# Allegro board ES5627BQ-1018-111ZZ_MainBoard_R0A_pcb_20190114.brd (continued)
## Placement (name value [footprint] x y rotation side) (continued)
C589  22uF/6.3V  [CC0603]  67.46 66.4 90 bottom
C590  22uF/6.3V  [CC0603]  71.78 66.39 90 top
C591  @5pF  [CC0402]  75.47 71.48 180 top
C592  @5pF  [CC0402]  74.44 71.48 180 top
C593  @5pF  [CC0402]  77.44 65.64 180 top
C594  @5pF  [CC0402]  75.41 65.64 180 top
C595  22uF/6.3V  [CC0603]  79.97 66.39 90 bottom
C596  22uF/6.3V  [CC0603]  84.23 66.33 90 top
C597  @5pF  [CC0402]  86.89 71.35 180 top
C598  @5pF  [CC0402]  85.86 71.35 180 top
C599  @5pF  [CC0402]  89.49 65.51 180 top
C600  @5pF  [CC0402]  88.48 65.51 180 top
C601  22uF/6.3V  [CC0603]  110.79 66.39 90 bottom
C602  22uF/6.3V  [CC0603]  115.11 66.39 90 top
C603  @5pF  [CC0402]  118.75 65.05 180 top
C604  @5pF  [CC0402]  117.74 65.05 180 top
C605  @5pF  [CC0402]  120.75 70.57 180 top
C606  @5pF  [CC0402]  119.73 70.57 180 top
C607  22uF/6.3V  [CC0603]  123.36 66.39 90 bottom
C608  22uF/6.3V  [CC0603]  127.68 66.39 90 top
C609  22uF/6.3V  [CC0603]  131.63 66.27 90 bottom
C610  22uF/6.3V  [CC0603]  135.82 66.27 90 top
C611  @5pF  [CC0402]  144.94 65.64 180 top
C612  @5pF  [CC0402]  143.93 65.64 180 top
C613  @5pF  [CC0402]  147.04 71.48 180 top
C614  @5pF  [CC0402]  146.02 71.48 180 top
C615  22uF/6.3V  [CC0603]  149.52 66.4 90 bottom
C616  22uF/6.3V  [CC0603]  153.84 66.39 90 top
C617  @5pF  [CC0402]  157.51 65.64 180 top
C618  @5pF  [CC0402]  156.5 65.64 180 top
C619  @5pF  [CC0402]  159.61 71.48 180 top
C620  @5pF  [CC0402]  158.59 71.48 180 top
C621  22uF/6.3V  [CC0603]  161.91 66.39 90 bottom
C622  22uF/6.3V  [CC0603]  166.35 66.4 90 top
C623  @5pF  [CC0402]  170.09 65.64 180 top
C624  @5pF  [CC0402]  169.07 65.64 180 top
C625  22uF/6.3V  [CC0603]  174.67 66.39 90 bottom
C626  22uF/6.3V  [CC0603]  178.99 66.39 90 top
C627  @5pF  [CC0402]  169.13 71.48 180 top
C628  @5pF  [CC0402]  170.15 71.48 180 top
C629  @5pF  [CC0402]  182.79 71.48 180 top
C630  @5pF  [CC0402]  181.77 71.48 180 top
C631  @5pF  [CC0402]  183.8 71.48 180 top
C632  @5pF  [CC0402]  184.82 71.48 180 top
C633  22uF/6.3V  [CC0603]  187.31 66.39 90 bottom
C634  22uF/6.3V  [CC0603]  191.62 66.39 90 top
C635  @5pF  [CC0402]  193.01 76.46 180 top
C636  @5pF  [CC0402]  195.23 65.49 180 top
C637  2.2uF(25V/10%)  [CC0603]  236.49 64.91 90 bottom
C638  0.1uF/16V  [CC0402]  13.45 71.34 180 top
C639  0.1uF/16V  [CC0402]  14.47 71.34 180 top
C640  0.1uF/16V  [CC0402]  15.48 71.34 180 top
C641  0.1uF/16V  [CC0402]  16.52 71.34 180 top
C642  0.1uF/16V  [CC0402]  17.54 71.34 180 top
C643  0.1uF/16V  [CC0402]  18.56 71.34 180 top
C644  0.1uF/16V  [CC0402]  16.55 65.64 180 top
C645  0.1uF/16V  [CC0402]  17.56 65.64 180 top
C646  0.1uF/16V  [CC0402]  18.56 65.64 180 top
C647  @5pF  [CC0402]  63.03 71.48 180 top
C648  @5pF  [CC0402]  62 71.48 180 top
C649  @5pF  [CC0402]  64.99 65.64 180 top
C650  @5pF  [CC0402]  62.96 65.64 180 top
C651  22uF/6.3V  [CC0603]  29.87 66.39 90 bottom
C652  22uF/6.3V  [CC0603]  34.19 66.39 90 top
C653  22uF/6.3V  [CC0603]  42.32 66.4 90 bottom
C654  22uF/6.3V  [CC0603]  46.7 66.39 270 bottom
C655  22uF/6.3V  [CC0603]  54.95 66.4 90 bottom
C656  22uF/6.3V  [CC0603]  59.27 66.39 270 bottom
C657  @5pF  [CC0402]  142.19 65.56 180 top
C658  @5pF  [CC0402]  141.18 65.56 180 top
C659  @5pF  [CC0402]  142.26 71.4 180 top
C660  @5pF  [CC0402]  141.24 71.4 180 top
C661  @5pF  [CC0402]  27.07 65.62 180 top
C662  @5pF  [CC0402]  25.04 65.62 180 top
C663  @5pF  [CC0402]  36.86 71.48 180 top
C664  @5pF  [CC0402]  38.9 71.48 180 top
C665  @5pF  [CC0402]  39.85 65.64 180 top
C666  @5pF  [CC0402]  38.83 65.64 180 top
C667  @5pF  [CC0402]  50.45 71.48 180 top
C668  @5pF  [CC0402]  49.42 71.48 180 top
C669  @5pF  [CC0402]  52.42 65.64 180 top
C670  @5pF  [CC0402]  51.41 65.64 180 top
C671  0.1uF/16V  [CC0402]  67.08 65.13 90 bottom
C672  0.1uF/16V  [CC0402]  72.29 65.12 90 top
C673  0.1uF/16V  [CC0402]  79.46 65.12 90 bottom
C674  0.1uF/16V  [CC0402]  84.73 65.13 90 top
C675  0.1uF/16V  [CC0402]  110.28 65.12 90 bottom
C676  0.1uF/16V  [CC0402]  115.61 65.12 90 top
C677  0.1uF/16V  [CC0402]  122.85 65.12 90 bottom
C678  0.1uF/16V  [CC0402]  128.19 65.12 90 top
C679  0.1uF/16V  [CC0402]  130.99 65 90 bottom
C680  0.1uF/16V  [CC0402]  136.33 65 90 top
C681  0.1uF/16V  [CC0402]  149.02 65.13 90 bottom
C682  0.1uF/16V  [CC0402]  154.35 65.12 90 top
C683  0.1uF/16V  [CC0402]  161.52 65.12 90 bottom
C684  0.1uF/16V  [CC0402]  166.83 65.12 90 top
C685  0.1uF/16V  [CC0402]  174.16 65.12 90 bottom
C686  0.1uF/16V  [CC0402]  179.5 65.12 90 top
C687  0.1uF/16V  [CC0402]  186.8 65.12 90 bottom
C688  0.1uF/16V  [CC0402]  192.13 65.12 90 top
C689  0.1uF/16V  [CC0402]  29.36 65.12 90 bottom
C690  0.1uF/16V  [CC0402]  34.7 65.12 90 top
C691  0.1uF/16V  [CC0402]  41.93 65.06 90 bottom
C692  0.1uF/16V  [CC0402]  47.2 65.12 270 bottom
C693  0.1uF/16V  [CC0402]  54.51 65.13 90 bottom
C694  0.1uF/16V  [CC0402]  59.78 65.12 270 bottom
C711  @4pF  [CC0402]  248.78 101.67 90 top
C712  @4pF  [CC0402]  250.67 101.67 270 top
C713  @4pF  [CC0402]  246.88 101.67 270 top
C714  @4pF  [CC0402]  244.99 101.67 90 top
C715  @4pF  [CC0402]  258.27 101.67 90 top
C716  @4pF  [CC0402]  256.38 101.67 270 top
C717  @4pF  [CC0402]  252.59 101.67 270 top
C718  @4pF  [CC0402]  254.49 101.67 90 top
C724  0.1uF/16V  [CC0402]  266.35 61.38 180 top
C725  0.1uF/16V  [CC0402]  265.33 61.38 180 top
C735  0.1uF/16V  [CC0402]  264.32 61.38 180 top
C736  0.1uF/16V  [CC0402]  267.36 61.38 180 top
C737  0.1uF/16V  [CC0402]  248.57 67.79 180 bottom
C738  0.1uF/16V  [CC0402]  239.37 76.55 0 top
C739  0.1uF/16V  [CC0402]  240.9 76.55 0 top
C753  0.1UF/50V  [CC0603]  95.82 106.83 270 top
C754  10nF/ 50V  [CC0402]  95.82 105.61 90 top
C771  1uF/16V  [CC0603]  143.41 95.78 270 top
C772  1uF/16V  [CC0603]  143.41 94.32 270 top
C773  10uF/16V  [CC0805]  227.7 134.95 180 top
C774  100pF  [CC0402]  237.13 136.85 0 top
C775  0.1uF/16V  [CC0402]  228.12 137.82 180 top
C776  0.1uF 16V  [CC0402]  224.68 134.67 0 top
C777  0.1uF/16V  [CC0402]  236.12 134.84 0 top
C778  10uF/10V  [CC0402]  235.1 134.83 0 top
C779  10nF  [CC0402]  234.19 113.63 180 bottom
C781  10nF  [CC0402]  232.16 113.63 180 bottom
C783  10nF  [CC0402]  229.17 113.63 180 bottom
C785  10nF  [CC0402]  227.16 113.62 180 bottom
C796  @5pF  [CC0402]  26.05 65.62 180 top
C797  @5pF  [CC0402]  24.02 65.62 180 top
C798  @5pF  [CC0402]  36.8 65.64 180 top
C799  @5pF  [CC0402]  37.82 65.64 180 top
C800  @5pF  [CC0402]  37.88 71.48 180 top
C801  @5pF  [CC0402]  39.91 71.48 180 top
C802  @5pF  [CC0402]  49.36 65.64 180 top
C803  @5pF  [CC0402]  50.39 65.64 180 top
C804  @5pF  [CC0402]  52.49 71.48 180 top
C805  @5pF  [CC0402]  51.47 71.48 180 top
C806  @5pF  [CC0402]  61.93 65.64 180 top
C807  @5pF  [CC0402]  63.98 65.64 180 top
C808  @5pF  [CC0402]  64.04 71.48 180 top
C809  @5pF  [CC0402]  65.06 71.48 180 top
C810  @5pF  [CC0402]  74.38 65.64 180 top
C811  @5pF  [CC0402]  76.42 65.64 180 top
C812  @5pF  [CC0402]  76.49 71.48 180 top
C813  @5pF  [CC0402]  77.5 71.48 180 top
C814  @5pF  [CC0402]  86.43 65.51 180 top
C815  @5pF  [CC0402]  87.46 65.51 180 top
C816  @5pF  [CC0402]  87.9 71.35 180 top
C817  @5pF  [CC0402]  88.92 71.35 180 top
C818  @5pF  [CC0402]  117.7 70.57 180 top
C819  @5pF  [CC0402]  118.72 70.57 180 top
C820  @5pF  [CC0402]  119.77 65.05 180 top
C821  @5pF  [CC0402]  120.79 65.05 180 top
C822  @5pF  [CC0402]  139.21 71.4 180 top
C823  @5pF  [CC0402]  140.22 71.4 180 top
C824  @5pF  [CC0402]  140.16 65.56 180 top
C825  @5pF  [CC0402]  139.15 65.56 180 top
C826  @5pF  [CC0402]  143.99 71.48 180 top
C827  @5pF  [CC0402]  145 71.48 180 top
C828  @5pF  [CC0402]  145.96 65.64 180 top
C829  @5pF  [CC0402]  146.97 65.64 180 top
C830  @5pF  [CC0402]  156.56 71.48 180 top
C831  @5pF  [CC0402]  157.58 71.48 180 top
C832  @5pF  [CC0402]  158.53 65.64 180 top
C833  @5pF  [CC0402]  159.55 65.64 180 top
C834  @5pF  [CC0402]  172.12 65.64 180 top
C835  @5pF  [CC0402]  171.17 71.48 180 top
C836  @5pF  [CC0402]  171.1 65.64 180 top
C837  @5pF  [CC0402]  172.18 71.48 180 top
C838  @5pF  [CC0402]  181.71 65.64 180 top
C839  @5pF  [CC0402]  182.72 65.64 180 top
C840  @5pF  [CC0402]  183.74 65.64 180 top
C841  @5pF  [CC0402]  184.76 65.64 180 top
C842  @5pF  [CC0402]  194.19 65.49 180 top
C843  @5pF  [CC0402]  196.29 65.48 180 top
C844  0.1uF/16V  [CC0402]  182.14 147.67 90 bottom
C845  0.1uF/16V  [CC0402]  182.14 146.65 90 bottom
C846  0.1uF/16V  [CC0402]  182.12 145.65 90 bottom
C847  270uF/16V  [CAPALE_6D3PI_5D6_2SP_6D6WL7D6H]  190.41 131.73 90 top
C848  22uF/16V  [CC1206]  198.24 136.55 90 bottom
C849  0.1uF/16V  [CC0402]  197.96 139.99 270 bottom
C850  0.1uF/16V  [CC0402]  207 148.89 90 top
C851  22uF/16V  [CC1206]  207.19 150.9 90 bottom
C852  270uF/16V  [CAPALE_6D3PI_5D6_2SP_6D6WL7D6H]  208.03 156.01 90 bottom
C853  0.1uF/16V  [CC0402]  132.56 256.77 270 bottom
C854  0.1uF/16V  [CC0402]  132.56 257.79 270 bottom
C855  0.1uF/16V  [CC0402]  124.74 241.59 90 bottom
C856  0.1uF/16V  [CC0402]  124.74 240.57 90 bottom
C857  0.1uF/16V  [CC0402]  132.56 255.76 270 bottom
C858  0.1uF/16V  [CC0402]  124.74 239.56 90 bottom
C859  0.1uF/16V  [CC0402]  124.74 242.61 90 bottom
C860  0.1uF  [CC0402]  263.68 87.54 180 top
C863  1000pF  [CC0402]  250.35 65.19 270 bottom
C864  0.1uF  [CC0402]  234.53 198.45 0 bottom
C865  0.1uF  [CC0402]  236.54 183.72 0 top
C866  0.1uF  [CC0402]  229.45 189.01 270 bottom
C867  0.1uF  [CC0402]  235.87 190.79 90 bottom
C868  0.1uF  [CC0402]  235.93 196 90 bottom
C869  0.1uF  [CC0402]  187.6 177.39 90 top
C870  0.1uF  [CC0402]  231.99 198.45 180 bottom
C871  4.7uF  [CC0402]  234.5 183.72 0 top
C872  4.7uF  [CC0402]  231.51 183.73 0 top
C873  0.1uF  [CC0402]  232.5 183.72 0 top
C874  0.1uF  [CC0402]  235.52 183.72 0 top
C875  4.7uF  [CC0402]  227.45 197.49 90 bottom
C876  0.1uF/16V  [CC0402]  229.52 193.01 270 bottom
C877  0.1uF/16V  [CC0402]  227.45 196.5 90 bottom
C878  10uF  [CC0402]  228.59 169.62 0 bottom
C879  0.1uF  [CC0402]  227.57 169.62 0 bottom
C880  18pF  [CC0402]  226.96 184.22 270 top
C881  0.1uF  [CC0402]  223.83 163.9 0 bottom
C882  0.1uF  [CC0402]  223.47 167.03 180 bottom
C883  0.1uF  [CC0402]  227.08 163.85 0 bottom
C884  18pF  [CC0402]  230.03 184.22 270 top
C885  @4pF  [CC0402]  234.87 110.63 270 top
C886  @4pF  [CC0402]  236.77 110.63 90 top
C887  @4pF  [CC0402]  231.06 110.63 270 top
C888  @4pF  [CC0402]  232.96 110.63 90 top
C889  0.1uF/16V  [CC0402]  237.33 75.41 90 bottom
C890  @4pF  [CC0402]  229.15 110.63 270 top
C891  @4pF  [CC0402]  227.18 110.63 90 top
C892  @4pF  [CC0402]  225.28 110.63 270 top
C893  @4pF  [CC0402]  223.37 110.63 90 top
C894  0.1uF  [CC0402]  226.79 94.14 90 bottom
C895  10nF  [CC0402]  230.6 94.14 270 bottom
C896  1000pF  [CC0402]  222.98 94.14 270 bottom
C897  1000pF  [CC0402]  235.42 74.39 90 bottom
C898  0.1uF  [CC0402]  259.93 87.54 180 top
C899  0.1uF  [CC0402]  256.64 84.81 90 bottom
C900  0.1uF  [CC0402]  252.89 84.81 90 bottom
C901  10uF  [CC0402]  103.34 228.62 0 bottom
C904  0.1uF/16V  [CC0402]  119.48 204.33 0 top
C905  0.1uF/16V  [CC0402]  118.47 204.35 0 top
C908  0.1uF/16V  [CC0402]  138.23 181.97 270 top
C909  0.1uF/16V  [CC0402]  138.23 183.17 270 top
C914  0.1uF/16V  [CC0402]  157.1 170.19 90 bottom
C915  1uF  [CC0402]  156.07 186.18 180 top
C916  1uF  [CC0402]  161.13 178.92 90 top
C917  0.1uF/16V  [CC0402]  146.26 189.3 180 top
C918  0.1uF/16V  [CC0402]  145.25 189.31 180 top
C919  10nF  [CC0402]  43.89 207.66 90 top
C922  10nF  [CC0402]  108.04 178.72 270 top
C923  1uF  [CC0402]  108.04 177.71 270 top
C924  10nF  [CC0402]  142.71 165.39 0 top
C925  0.1uF/16V  [CC0402]  108.04 179.74 90 top
C926  0.1uF/16V  [CC0402]  43.89 208.67 270 top
C927  0.1uF/16V  [CC0402]  143.73 165.39 180 top
C928  0.1uF/16V  [CC0402]  161.13 179.93 90 top
C929  0.1uF/16V  [CC0402]  146.66 179.9 270 bottom
C930  0.1uF/16V  [CC0402]  147.41 175.61 270 bottom
C931  0.1uF/16V  [CC0402]  145.07 184.34 90 bottom
C932  0.1uF/16V  [CC0402]  144.24 175.36 90 bottom
C933  0.1uF/16V  [CC0402]  146.71 177.13 270 bottom
C934  0.1uF/16V  [CC0402]  147.79 186.27 180 top
C935  0.1uF/16V  [CC0402]  147.68 172.97 0 bottom
C936  0.1uF/16V  [CC0402]  152.36 172.97 0 bottom
C937  0.1uF/16V  [CC0402]  150.1 172.96 0 bottom
C938  0.1uF/16V  [CC0402]  156.05 183.36 180 bottom
C939  0.1uF/16V  [CC0402]  158.02 180.69 90 bottom
C940  0.1uF/16V  [CC0402]  158.09 171.65 180 bottom
C941  0.1uF/16V  [CC0402]  146.74 170.5 180 bottom
C942  0.1uF/16V  [CC0402]  151.36 172.97 0 bottom
C943  0.1uF/16V  [CC0402]  146.53 185.82 0 bottom
C944  0.1uF/16V  [CC0402]  148.36 183.3 180 bottom
C945  0.1uF/16V  [CC0402]  153.8 172.69 270 bottom
C946  0.1uF/16V  [CC0402]  144.24 181.39 90 bottom
C947  0.1uF/16V  [CC0402]  144.24 174.34 90 bottom
C948  0.1uF/16V  [CC0402]  149.08 172.96 0 bottom
C949  0.1uF/16V  [CC0402]  146.7 178.24 270 bottom
C952  0.1uF/16V  [CC0402]  255.04 48.49 0 top
C953  0.1uF/16V  [CC0402]  255.04 48.49 180 bottom
C954  0.1uF/16V  [CC0402]  213.13 26.16 180 bottom
C955  0.1uF/16V  [CC0402]  213.6 9.81 90 bottom
C956  0.1uF/16V  [CC0402]  256.06 48.49 180 bottom
C957  0.1uF/16V  [CC0402]  223.55 33.32 270 bottom
C958  0.1uF/16V  [CC0402]  228.61 33.4 180 top
C959  0.1uF/16V  [CC0402]  223.57 33.31 90 top
C960  0.1uF/16V  [CC0402]  137.04 92.89 180 top
C961  0.1uF/16V  [CC0402]  138.03 92.88 180 top
C962  0.1uF/16V  [CC0402]  139.03 92.87 180 top
C963  0.1uF/16V  [CC0402]  140.03 92.87 180 top
C964  0.1uF/16V  [CC0402]  198.75 92.97 180 top
C965  0.1uF/16V  [CC0402]  199.74 92.97 180 top
C966  0.1uF/16V  [CC0402]  201.74 92.98 180 top
C967  0.1uF/16V  [CC0402]  200.74 92.98 180 top
C968  0.1uF/16V  [CC0402]  265.27 189.67 180 top
C969  0.1uF/16V  [CC0402]  266.26 189.67 180 top
C970  0.1uF/16V  [CC0402]  264.26 189.66 180 top
C971  0.1uF/16V  [CC0402]  263.27 189.66 180 top
C972  0.1uF/16V  [CC0402]  206.98 112.37 90 top
C973  0.1uF/16V  [CC0402]  206.98 113.38 90 top
C974  0.1uF/16V  [CC0402]  206.98 111.29 90 top
C975  0.1uF/16V  [CC0402]  206.98 114.4 90 top
C976  0.1uF/16V  [CC0402]  131.26 116.42 180 top
C977  0.1uF/16V  [CC0402]  132.28 116.42 180 top
C978  0.1uF/16V  [CC0402]  133.27 116.41 180 top
C979  0.1uF/16V  [CC0402]  134.28 116.41 180 top
C980  0.1uF/16V  [CC0402]  129.15 234.71 180 top
C981  0.1uF/16V  [CC0402]  130.16 234.71 180 top
C982  0.1uF/16V  [CC0402]  131.16 234.71 180 top
C983  0.1uF/16V  [CC0402]  132.16 234.7 180 top
C984  0.1uF/16V  [CC0402]  63.59 215.49 90 top
C985  0.1uF/16V  [CC0402]  63.59 217.52 270 top
C986  0.1uF/16V  [CC0402]  103.53 251.11 270 bottom
C987  0.1uF/16V  [CC0402]  138.22 175.3 270 top
C988  0.1uF/16V  [CC0402]  138.23 176.5 270 top
C989  0.1uF/16V  [CC0402]  207.82 10.14 270 bottom
C990  0.1uF/16V  [CC0402]  222.22 42.95 180 bottom
C991  0.1uF/16V  [CC0402]  222.23 40.17 0 top
C992  0.1uF/16V  [CC0402]  211.09 18.23 0 bottom
C993  0.1uF/16V  [CC0402]  246.47 147.39 180 top
C994  0.1uF/16V  [CC0402]  247.46 147.39 180 top
C995  0.1uF/16V  [CC0402]  245.46 147.39 180 top
C996  0.1uF/16V  [CC0402]  248.45 147.39 180 top
C997  0.1uF/16V  [CC0402]  207.46 147.24 180 top
C998  0.1uF/16V  [CC0402]  212.64 139.42 90 top
C999  0.1uF/16V  [CC0402]  212.64 140.46 90 top
C1000  0.1uF/16V  [CC0402]  208.5 147.24 180 top
C1001  0.1uF/16V  [CC0402]  123.13 136.12 270 top
C1002  0.1uF/16V  [CC0402]  123.13 135.07 270 top
C1003  0.1uF/16V  [CC0402]  126.66 133.45 0 top
C1004  0.1uF/16V  [CC0402]  127.7 133.45 0 top
CB2  0.1uF/16V  [CC0402]  90.29 182.51 270 bottom
CB3  10uF/6.3V  [CC0603]  90.61 182.45 90 top
CB4  0.1uF/16V  [CC0402]  61.69 223.24 0 top
CB5  0.1uF/16V  [CC0402]  86.92 183.59 180 bottom
CB6  10uF/6.3V  [CC0603]  92.96 183.57 0 top
CB7  9pF/50V  [CC0402]  82.42 183.83 180 top
CB8  9pF/50V  [CC0402]  84.45 183.83 0 top
CB9  22uF  [CC0603]  86.88 183.27 0 top
CB10  10pF  [CC0402]  91.56 184.08 180 top
CB12  0.1uF/16V  [CC0402]  37.43 238.92 0 bottom
CB13  0.1uF/16V  [CC0402]  33.05 238.92 0 bottom
CB21  0.1UF 50V  [CC0603]  140.43 232.26 0 top
CB24  0.1uF/16V  [CC0402]  57.81 223.24 180 top
CB25  10uF/6.3V  [CC0603]  89.78 186.62 0 top
CB26  22uF  [CC0603]  91.43 186.62 0 top
CB27  0.1uF/16V  [CC0402]  167.55 173.03 180 top
CB28  22uF/6.3V  [CC0805]  209.8 207.02 0 bottom
CB29  10uF/6.3V  [CC0603]  168.73 173.29 0 top
CB30  0.1uF/16V  [CC0402]  33.18 223.11 180 top
CB31  0.1uF/16V  [CC0402]  58.83 223.24 0 top
CB32  0.1uF/16V  [CC0402]  90.04 188.65 90 top
CB33  0.1uF 16V  [CC0402]  231.06 224.09 270 bottom
CB34  0.1uF/16V  [CC0402]  80.67 189.58 0 bottom
CB35  0.1uF/16V  [CC0402]  49.94 238.92 0 bottom
CB36  0.1uF/16V  [CC0402]  37.37 223.11 180 top
CB38  0.1uF/16V  [CC0402]  70.96 238.92 0 bottom
CB39  0.1uF/16V  [CC0402]  45.81 238.92 0 bottom
CB42  0.1uF/16V  [CC0402]  83.18 193.99 180 top
CB43  0.1uF/16V  [CC0402]  85.72 193.99 180 top
CB44  0.1uF/16V  [CC0402_22X22_8OCT]  191.06 199.6 180 bottom
CB45  0.1uF/16V  [CC0402_22X22_8OCT]  206.04 199.6 180 bottom
CB46  10uF/6.3V  [CC0603]  84.45 194.49 180 top
CB47  10uF/6.3V  [CC0603]  86.99 194.49 180 top
CB48  22uF  [CC0603]  88.51 194.49 180 top
CB49  10uF/6.3V  [CC0603]  91.56 194.49 0 top
CB50  10pF  [CC0402]  92.93 194.66 180 top
CB51  0.1uF/16V  [CC0402_22X22_8OCT]  190.04 198.58 0 bottom
CB52  10uF/10V  [CC0402]  19.02 178.03 0 bottom
CB53  0.1uF/16V  [CC0402]  20.03 178.03 0 bottom
CB54  0.1uF/16V  [CC0402]  21.05 178.03 0 bottom
CB55  1uF/25V  [CC0402]  22.06 178.03 0 bottom
CB56  0.1uF/16V  [CC0402]  22.95 178.03 0 bottom
CB57  0.1uF/16V  [CC0402]  24.1 178.03 0 bottom
CB58  22nF/16V  [CC0402]  24.98 178.03 180 bottom
CB59  1uF/25V  [CC0402]  26 178.03 0 bottom
CB60  0.01uF/25V  [CC0402]  27.02 178.03 180 bottom
CB61  10uF/10V  [CC0402]  28.03 178.03 0 bottom
CB62  1uF/25V  [CC0402]  30.06 178.03 0 bottom
CB63  10uF/10V  [CC0402]  31.08 178.03 0 bottom
CB64  22nF/16V  [CC0402]  32.12 178.03 180 bottom
CB65  0.1uF/16V  [CC0402]  83.4 177.9 0 bottom
CB66  0.1uF/16V  [CC0402]  84.42 177.9 0 bottom
CB67  0.01uF/25V  [CC0402]  85.44 177.9 180 bottom
CB68  0.01uF/25V  [CC0402]  86.45 177.9 180 bottom
CB69  0.1uF/16V  [CC0402]  87.47 177.9 0 bottom
CB70  0.1uF/16V  [CC0402]  88.48 177.9 0 bottom
CB71  22nF/16V  [CC0402]  92.68 177.9 180 bottom
CB72  0.1uF/16V  [CC0402_22X22_8OCT]  207.57 197.06 270 bottom
CB73  1uF/25V  [CC0402]  81.32 177.87 0 bottom
CB74  22nF/16V  [CC0402]  82.34 177.87 180 bottom
CB75  10uF/10V  [CC0402]  90.52 177.87 0 bottom
CB76  0.1uF/16V  [CC0402]  91.66 177.87 0 bottom
CB77  0.1uF/16V  [CC0402]  69.59 177.8 0 bottom
CB78  22nF/16V  [CC0402]  70.58 177.8 180 bottom
CB79  0.1uF/16V  [CC0402]  60.42 177.77 0 bottom
CB80  22nF/16V  [CC0402]  61.43 177.77 180 bottom
CB81  10uF/10V  [CC0402]  62.45 177.77 0 bottom
CB82  0.1uF/16V  [CC0402]  63.47 177.77 0 bottom
CB83  0.1uF/16V  [CC0402]  64.48 177.77 0 bottom
CB84  1uF/25V  [CC0402]  65.5 177.77 0 bottom
CB85  0.01uF/25V  [CC0402]  66.51 177.77 180 bottom
CB86  22nF/16V  [CC0402]  67.53 177.77 180 bottom
CB87  10uF/10V  [CC0402]  68.55 177.77 0 bottom
CB90  0.01uF/25V  [CC0402]  96.74 174.85 270 bottom
CB92  0.1uF/16V  [CC0402_22X22_8OCT]  197.03 193.63 180 bottom
CB101  0.1uF/16V  [CC0402_22X22_8OCT]  200.58 193.12 270 bottom
CB104  0.1uF/16V  [CC0402_22X22_8OCT]  199.06 192.61 180 bottom
CB108  0.1uF/16V  [CC0402_22X22_8OCT]  195.5 192.1 270 bottom
CB109  0.1uF/16V  [CC0402_22X22_8OCT]  201.5 192.08 90 bottom
CB110  1uF/25V  [CC0402]  85.18 172.69 270 bottom
CB113  0.1uF/16V  [CC0402_22X22_8OCT]  197.03 191.59 0 bottom
CB114  0.1uF/16V  [CC0402_22X22_8OCT]  200.08 191.59 180 bottom
CB118  22nF/16V  [CC0402]  40.86 172.06 0 bottom
CB119  1uF/25V  [CC0402]  41.88 172.06 0 bottom
CB120  0.01uF/25V  [CC0402]  101.44 172.69 90 bottom
CB121  0.1uF/16V  [CC0402_22X22_8OCT]  201.47 191.06 270 bottom
CB122  0.1uF/16V  [CC0402]  81.37 171.88 0 bottom
CB124  1uF/25V  [CC0402]  92.19 171.5 0 bottom
CB125  0.1uF/16V  [CC0402]  75.66 171.42 90 bottom
CB128  0.1uF/16V  [CC0402_22X22_8OCT]  196.52 190.2 90 bottom
CB129  0.1uF/16V  [CC0402_22X22_8OCT]  200.58 190.2 270 bottom
CB130  22nF/16V  [CC0402]  41.24 170.66 270 bottom
CB131  1uF/25V  [CC0402]  49.75 170.66 90 bottom
CB134  0.1uF/16V  [CC0402]  90.41 170.53 0 bottom
CB135  22nF/16V  [CC0402]  75.66 170.41 270 bottom
CB136  22nF/16V  [CC0402]  80.99 170.41 90 bottom
CB138  0.1uF/16V  [CC0402_22X22_8OCT]  195.1 189.56 0 bottom
CB139  0.01uF/25V  [CC0402]  14.95 170.28 90 bottom
CB140  22uF/6.3V  [CC0805]  198.55 189.44 180 bottom
CB141  1uF/25V  [CC0402]  60.04 171.52 90 bottom
CB152  1uF/25V  [CC0402]  92.19 169.62 180 bottom
CB153  0.1uF/16V  [CC0402_22X22_8OCT]  196.09 188.57 180 bottom
CB154  22uF/6.3V  [CC0603]  41.75 169.39 270 bottom
CB155  0.1uF/16V  [CC0402_22X22_8OCT]  201.09 188.55 180 bottom
CB156  0.01uF/25V  [CC0402]  12.41 169.26 270 bottom
CB157  0.01uF/25V  [CC0402]  60.04 170.51 90 bottom
CB159  0.1uF/16V  [CC0402]  101.03 168.78 0 bottom
CB160  0.1uF/16V  [CC0402]  90.49 168.42 0 bottom
CB161  0.1uF/16V  [CC0402_22X22_8OCT]  197.03 187.53 0 bottom
CB162  0.1uF/16V  [CC0402_22X22_8OCT]  200.08 187.53 0 bottom
CB166  0.01uF/25V  [CC0402]  12.41 168.12 270 bottom
CB167  0.01uF/25V  [CC0402]  60.04 169.52 90 bottom
CB170  0.1uF/16V  [CC0402_22X22_8OCT]  198.55 187.05 270 bottom
CB172  0.01uF/25V  [CC0402]  91.79 167.74 0 bottom
CB173  0.01uF/25V  [CC0402]  49.09 167.51 180 bottom
CB175  22nF/16V  [CC0402]  50.08 167.49 180 bottom
CB176  1uF/25V  [CC0402]  75.66 167.36 90 bottom
CB177  0.01uF/25V  [CC0402]  60.16 167.23 270 bottom
CB181  1uF/25V  [CC0402]  101.06 166.93 180 bottom
CB182  1uF/25V  [CC0402]  69.89 166.85 180 bottom
CB183  0.01uF/25V  [CC0402]  71.34 166.82 270 bottom
CB185  1uF/25V  [CC0402]  90.39 166.55 180 bottom
CB186  0.01uF/25V  [CC0402]  12.67 166.34 90 bottom
CB193  22nF/16V  [CC0402]  91.79 165.83 0 bottom
CB195  0.1uF/16V  [CC0402]  71.34 165.81 270 bottom
CB196  0.01uF/25V  [CC0402]  41.24 165.71 270 bottom
CB197  0.01uF/25V  [CC0402]  81.37 165.71 0 bottom
CB198  0.1uF/16V  [CC0402]  49.06 165.61 180 bottom
CB199  1uF/25V  [CC0402]  50.08 165.61 180 bottom
CB201  0.1uF/16V  [CC0402]  12.67 165.33 90 bottom
CB202  0.1uF/16V  [CC0402]  14.95 165.33 270 bottom
CB203  0.1uF/16V  [CC0402]  60.16 165.33 270 bottom
CB205  0.1uF/16V  [CC0402]  101.06 165.02 180 bottom
CB206  0.01uF/25V  [CC0402]  69.89 164.97 180 bottom
CB208  0.01uF/25V  [CC0402]  62.35 164.82 90 bottom
CB209  1uF/25V  [CC0402]  68.44 164.82 270 bottom
CB210  0.01uF/25V  [CC0402]  82.79 164.82 90 bottom
CB211  22nF/16V  [CC0402]  93.23 164.82 90 bottom
CB212  1uF/25V  [CC0402]  99.28 164.82 270 bottom
CB213  0.01uF/25V  [CC0402]  88.74 164.79 270 bottom
CB214  22nF/16V  [CC0402]  41.24 164.69 270 bottom
CB217  1uF/25V  [CC0402]  90.36 164.64 180 bottom
CB218  0.1uF/16V  [CC0402]  87.27 164.29 180 bottom
CB221  1uF/25V  [CC0402]  14.95 164.18 90 bottom
CB224  0.1uF/16V  [CC0402_22X22_8OCT]  190.55 183.09 270 bottom
CB225  0.1uF/16V  [CC0402_22X22_8OCT]  206.55 183.09 90 bottom
CB226  22nF/16V  [CC0402]  49.11 163.8 0 bottom
CB227  1uF/25V  [CC0402]  50.13 163.8 0 bottom
CB228  22nF/16V  [CC0402]  81.37 163.8 0 bottom
CB229  0.1uF/16V  [CC0402]  95.22 163.8 0 bottom
CB230  0.1uF/16V  [CC0402]  65.5 163.68 0 bottom
CB231  0.01uF/25V  [CC0402]  64.48 163.65 0 bottom
CB232  22nF/16V  [CC0402]  41.24 163.55 270 bottom
CB233  0.1uF/16V  [CC0402]  91.74 163.4 0 bottom
CB234  0.01uF/25V  [CC0402]  101.5 162.6 270 bottom
CB235  0.01uF/25V  [CC0402]  69.89 163.09 180 bottom
CB236  22nF/16V  [CC0402]  84.81 162.94 0 bottom
CB239  0.1uF/16V  [CC0402_22X22_8OCT]  190.55 182.07 90 bottom
CB240  0.1uF/16V  [CC0402_22X22_8OCT]  206.55 182.07 270 bottom
CB241  0.01uF/25V  [CC0402]  59.25 162.89 180 bottom
CB242  1uF/25V  [CC0402]  60.26 162.89 180 bottom
CB243  0.1uF/16V  [CC0402]  61.28 162.89 180 bottom
CB244  0.1uF/16V  [CC0402]  71.34 162.79 90 bottom
CB246  22nF/16V  [CC0402]  90.39 162.76 180 bottom
CB247  0.1uF/16V  [CC0402]  41.24 162.53 270 bottom
CB253  22nF/16V  [CC0402]  49.5 162.41 90 bottom
CB254  0.1uF/16V  [CC0402]  14.95 162.28 90 bottom
CB257  0.1uF/16V  [CC0402]  66.77 162 180 bottom
CB258  22nF/16V  [CC0402]  78.2 161.9 0 bottom
CB260  0.1uF/16V  [CC0402]  96.61 161.77 180 bottom
CB261  1uF/25V  [CC0402]  97.63 161.77 180 bottom
CB262  0.1uF/16V  [CC0402]  64.23 161.64 180 bottom
CB263  22nF/16V  [CC0402]  70.45 161.64 270 bottom
CB265  0.1uF/16V  [CC0402]  49.5 161.52 90 bottom
CB266  1uF/25V  [CC0402]  80.36 161.52 0 bottom
CB267  0.1uF/16V  [CC0402]  81.37 161.52 0 bottom
CB268  1uF/25V  [CC0402]  91.71 161.34 0 bottom
CB269  0.01uF/25V  [CC0402]  101.5 158.6 270 bottom
CB270  1uF/25V  [CC0402]  101.5 161.64 270 bottom
CB271  22uF/6.3V  [CC0603]  65.5 161.14 180 bottom
CB273  22nF/16V  [CC0402]  14.95 161.01 90 bottom
CB274  1uF/25V  [CC0402]  54.07 161.01 270 bottom
CB275  1uF/25V  [CC0402]  55.85 161.01 90 bottom
CB276  0.01uF/25V  [CC0402]  59.27 160.98 0 bottom
CB277  0.1uF/16V  [CC0402]  60.29 160.98 0 bottom
CB278  1uF/25V  [CC0402]  90.39 160.88 0 bottom
CB279  0.01uF/25V  [CC0402]  86.71 160.7 90 bottom
CB280  0.1uF/16V  [CC0402]  49.5 160.63 90 bottom
CB281  22nF/16V  [CC0402]  70.45 160.63 270 bottom
CB282  0.1uF/16V  [CC0402]  41.24 160.5 270 bottom
CB284  1uF/25V  [CC0402]  66.77 160.12 0 bottom
CB285  0.01uF/25V  [CC0402]  54.07 160.04 270 bottom
CB286  0.1uF/16V  [CC0402]  55.85 160.04 90 bottom
CB287  22nF/16V  [CC0402]  80.86 160.04 90 bottom
CB288  22nF/16V  [CC0402]  97.63 159.89 0 bottom
CB290  0.01uF/25V  [CC0402]  101.5 159.61 270 bottom
CB291  1uF/25V  [CC0402]  49.5 159.74 90 bottom
CB292  1uF/25V  [CC0402]  86.71 159.71 90 bottom
CB293  1uF/25V  [CC0402]  60.04 159.66 270 bottom
CB294  0.1uF/16V  [CC0402]  14.95 159.61 90 bottom
CB295  0.1uF/16V  [CC0402]  70.45 159.61 270 bottom
CB296  1uF/25V  [CC0402]  41.24 159.48 270 bottom
CB297  1uF/25V  [CC0402]  91.68 159.48 0 bottom
CB299  1uF/25V  [CC0402]  80.86 159.05 90 bottom
CB300  22nF/16V  [CC0402]  55.85 159.03 90 bottom
CB308  0.1uF/16V  [CC0402]  49.5 158.85 90 bottom
CB310  22nF/16V  [CC0402]  14.95 158.6 90 bottom
CB311  1uF/25V  [CC0402]  70.45 158.6 270 bottom
CB312  22nF/16V  [CC0402]  41.24 158.47 270 bottom
CB313  0.01uF/25V  [CC0402]  99.69 157.73 90 bottom
CB314  1uF/25V  [CC0402]  88.99 157.68 90 bottom
CB315  1uF/25V  [CC0402]  93.26 157.63 270 bottom
CB316  22nF/16V  [CC0402]  14.95 157.58 90 bottom
CB317  0.01uF/25V  [CC0402]  70.7 157.58 270 bottom
CB318  22nF/16V  [CC0402]  41.24 157.45 270 bottom
CB319  470uF/2V  [CAP_6D4_2SP_4D3W7D3L2D1H]  52.42 155.83 0 bottom
CB320  470uF/2V  [CAP_6D4_2SP_4D3W7D3L2D1H]  62.91 155.83 180 bottom
CB321  0.1uF/16V  [CC0402]  202.7 120.61 180 top
CB322  0.1uF/16V  [CC0402]  206.82 120.59 180 top
CB323  0.1uF/16V  [CC0402]  210.72 131.99 90 bottom
CB324  22uF/6.3V  [CC0603]  53.69 152.5 90 bottom
CB325  470uF/2V  [CAP_6D4_2SP_4D3W7D3L2D1H]  42.07 168.88 270 top
CB326  470uF/2V  [CAP_6D4_2SP_4D3W7D3L2D1H]  42 158.53 90 top
CB327  10uF/6.3V  [CC0603]  208.88 132.88 0 top
CB328  470uF/2V  [CAP_6D4_2SP_4D3W7D3L2D1H]  107.15 163.93 90 top
CB330  0.01uF/25V  [CC0402]  101.5 163.61 270 bottom
CB331  10uF/6.3V  [CC0805]  100.17 145.26 0 bottom
CB332  10uF/6.3V  [CC0805]  102.2 145.26 0 bottom
CB333  100uF/6.3V  [CC0805]  104.23 145.26 0 bottom
CB334  0.01uF/25V  [CC0402]  107.41 172.06 0 bottom
CB335  10uF/6.3V  [CC0805]  100.17 139.93 180 bottom
CB336  100uF/6.3V  [CC0805]  102.2 139.93 180 bottom
CB337  10uF/6.3V  [CC0805]  104.11 139.93 180 bottom
CB338  100uF/6.3V  [CC0805]  123.79 164.31 180 top
CB339  100uF/6.3V  [CC0805]  113.38 156.69 180 bottom
CB340  100uF/6.3V  [CC0805]  115.79 156.69 180 bottom
CB341  0.1uF/16V  [CC0402]  41.75 137.89 180 bottom
CB342  0.1uF/16V  [CC0402]  42.76 137.89 180 bottom
CB343  0.1uF/16V  [CC0402]  30.57 137.77 180 bottom
CB344  0.1uF/16V  [CC0402]  31.59 137.77 180 bottom
CB345  0.1uF/16V  [CC0402]  21.68 139.1 180 bottom
CB346  470uF/2V  [CAP_6D4_2SP_4D3W7D3L2D1H]  77.44 135.86 270 bottom
CB347  470uF/2V  [CAP_6D4_2SP_4D3W7D3L2D1H]  82.64 135.86 270 bottom
CB348  0.1uF/16V  [CC0402]  95.6 134.59 0 bottom
CB350  1uF/16V  [CC0402_22X22_8OCT]  29.72 134.22 270 bottom
CB352  22nF/16V  [CC0402_22X22_8OCT]  43.18 133.71 180 bottom
CB353  1uF/16V  [CC0402_22X22_8OCT]  24.19 133.66 0 bottom
CB354  1uF/16V  [CC0402_22X22_8OCT]  27.19 133.66 0 bottom
CB355  0.1uF/16V  [CC0402_22X22_8OCT]  33.19 133.66 180 bottom
CB356  22nF/16V  [CC0402_22X22_8OCT]  45.2 133.66 0 bottom
CB357  22nF/16V  [CC0402_22X22_8OCT]  48.2 133.66 0 bottom
CB358  22nF/16V  [CC0402_22X22_8OCT]  54.21 133.66 0 bottom
CB359  1uF/16V  [CC0402_22X22_8OCT]  52.2 133.58 0 bottom
CB360  100uF/6.3V  [CC0805]  118.37 156.63 180 bottom
CB361  100uF/6.3V  [CC0805]  123.66 156.53 0 top
CB362  100uF/6.3V  [CC0805]  123.9 156.16 180 bottom
CB363  0.1uF/16V  [CC0402_22X22_8OCT]  40.69 133.1 270 bottom
CB364  1uF/16V  [CC0402_22X22_8OCT]  21.18 132.66 0 bottom
CB365  0.1uF/16V  [CC0402_22X22_8OCT]  36.2 132.66 180 bottom
CB366  22uF /25V  [CC1206]  101.47 129.05 270 bottom
CB367  0.1uF/16V  [CC0402_22X22_8OCT]  37.72 132.18 90 bottom
CB369  22nF/16V  [CC0402_22X22_8OCT]  32.19 131.66 180 bottom
CB370  0.1uF/16V  [CC0402_22X22_8OCT]  50.21 131.66 0 bottom
CB371  100uF /6.3V  [CC1206]  115.92 156.18 0 top
CB372  @100uF /6.3V  [CC1206]  113.38 156.18 0 top
CB373  100uF /6.3V  [CC1206]  118.46 156.18 0 top
CB374  1uF/16V  [CC0402_22X22_8OCT]  40.64 131.17 270 bottom
CB375  22nF/16V  [CC0402_22X22_8OCT]  45.72 131.17 270 bottom
CB376  1uF/16V  [CC0402_22X22_8OCT]  25.69 131.16 90 bottom
CB377  0.1uF/16V  [CC0402_22X22_8OCT]  47.7 131.16 270 bottom
CB378  0.1uF/16V  [CC0402_22X22_8OCT]  52.71 131.16 270 bottom
CB379  1uF/16V  [CC0402_22X22_8OCT]  56.71 131.16 90 bottom
CB380  0.1uF/50V  [CC0402_22X22_8OCT]  21.59 131.04 270 bottom
CB381  2.2uF/16V  [CC0603]  96.87 131.04 0 bottom
CB383  0.1uF/16V  [CC0402]  165.57 131.09 90 bottom
CB384  1uF/16V  [CC0402_22X22_8OCT]  23.19 130.66 0 bottom
CB385  1uF/16V  [CC0402_22X22_8OCT]  29.19 130.66 0 bottom
CB386  0.1uF/16V  [CC0402_22X22_8OCT]  35.19 130.66 180 bottom
CB387  1uF/16V  [CC0402_22X22_8OCT]  54.21 130.66 180 bottom
CB388  1nF/50V  [CC0402]  95.6 130.66 180 bottom
CB389  22nF/16V  [CC0402_22X22_8OCT]  33.69 130.16 90 bottom
CB390  1uF/16V  [CC0402_22X22_8OCT]  25.19 129.66 0 bottom
CB391  22nF/16V  [CC0402_22X22_8OCT]  40.2 129.66 0 bottom
CB392  22nF/16V  [CC0402_22X22_8OCT]  43.2 129.66 0 bottom
CB393  22nF/16V  [CC0402_22X22_8OCT]  46.2 129.66 0 bottom
CB394  0.1uF/16V  [CC0402_22X22_8OCT]  24.26 129.64 0 bottom
CB395  0.1uF/16V  [CC0402_22X22_8OCT]  37.7 129.16 270 bottom
CB396  0.1uF/16V  [CC0402_22X22_8OCT]  51.71 129.16 90 bottom
CB397  0.1uF/16V  [CC0402_22X22_8OCT]  49.66 129.14 270 bottom
CB398  1uF/16V  [CC0402_22X22_8OCT]  28.19 128.66 0 bottom
CB399  1uF/16V  [CC0402_22X22_8OCT]  31.19 128.66 0 bottom
CB400  0.1uF/16V  [CC0402]  40.67 191.55 180 bottom
CB401  22nF/16V  [CC0402_22X22_8OCT]  33.69 128.16 270 bottom
CB402  1uF/16V  [CC0402_22X22_8OCT]  56.71 128.16 90 bottom
CB403  22nF/16V  [CC0402_22X22_8OCT]  52.71 128.12 270 bottom
CB404  1500pF  [CC0402]  110.03 129.07 90 bottom
CB405  22uF/10V  [CC1206]  76.29 127.73 180 bottom
CB406  22uF/25V  [CC1206]  78.58 127.73 0 bottom
CB407  22uF/10V  [CC1206]  80.86 127.73 180 bottom
CB408  0.047uF  [CC0402]  122.67 168.57 0 bottom
CB409  22nF/16V  [CC0402_22X22_8OCT]  42.2 127.65 0 bottom
CB410  1uF/16V  [CC0402_22X22_8OCT]  45.2 127.65 180 bottom
CB411  0.1uF/16V  [CC0402_22X22_8OCT]  48.2 127.65 0 bottom
CB412  22nF/16V  [CC0402_22X22_8OCT]  40.13 127.64 180 bottom
CB413  22uF /25V  [CC1206]  101.46 126.79 270 bottom
CB414  0.1uF/16V  [CC0402_22X22_8OCT]  30.69 127.15 270 bottom
CB415  0.1uF/16V  [CC0402_22X22_8OCT]  36.7 127.15 270 bottom
CB416  1uF/16V  [CC0402_22X22_8OCT]  53.72 127.1 270 bottom
CB417  @470pF  [CC0603]  42.15 190.59 180 bottom
CB418  22nF/16V  [CC0402_22X22_8OCT]  28.2 126.72 0 bottom
CB419  1uF/16V  [CC0402_22X22_8OCT]  27.19 126.65 0 bottom
CB420  0.1uF/16V  [CC0402_22X22_8OCT]  41.2 126.65 0 bottom
CB421  0.1uF/16V  [CC0402_22X22_8OCT]  21.72 126.09 90 bottom
CB422  470uF/ 2V  [CAP_6D4_2SP_4D3W7D3L2D1H]  84.67 125.83 90 bottom
CB423  0.1uF/16V  [CC0402_22X22_8OCT]  32.19 125.65 0 bottom
CB424  0.1uF/16V  [CC0402_22X22_8OCT]  37.2 125.65 0 bottom
CB425  22nF/16V  [CC0402_22X22_8OCT]  38.2 125.65 0 bottom
CB426  0.1uF/16V  [CC0402_22X22_8OCT]  44.2 125.65 0 bottom
CB427  0.1uF/16V  [CC0402_22X22_8OCT]  47.2 125.65 0 bottom
CB429  0.1uF/16V  [CC0402_22X22_8OCT]  48.72 125.17 270 bottom
CB430  0.1uF/16V  [CC0402_22X22_8OCT]  30.69 125.15 270 bottom
CB431  0.1uF/16V  [CC0402_22X22_8OCT]  33.69 125.15 270 bottom
CB432  0.1uF/16V  [CC0402_22X22_8OCT]  42.7 125.15 270 bottom
CB433  22nF/16V  [CC0402_22X22_8OCT]  45.7 125.15 270 bottom
CB434  1uF/16V  [CC0402_22X22_8OCT]  54.71 125.15 270 bottom
CB435  1uF/16V  [CC0402_22X22_8OCT]  56.71 125.15 90 bottom
CB436  0.1uF/16V  [CC0402_22X22_8OCT]  51.64 125.15 270 bottom
CB437  0.1uF/16V  [CC0402_22X22_8OCT]  40.72 125.07 90 bottom
CB438  @100uF /6.3V  [CC1206]  47.34 180.69 90 bottom
CB439  @100uF /6.3V  [CC1206]  47.34 178.34 90 bottom
CB440  0.1uF/50V  [CC0603]  254.09 161.77 270 bottom
CB441  0.1uF/16V  [CC0402]  60.8 124.81 90 bottom
CB442  22nF/16V  [CC0402_22X22_8OCT]  39.2 124.65 0 bottom
CB443  1uF/16V  [CC0402]  80.23 108.43 180 bottom
CB444  1uF/16V  [CC0402]  81.25 108.43 180 bottom
CB445  1uF/16V  [CC0402]  82.26 108.43 180 bottom
CB446  1uF/16V  [CC0402]  83.28 108.43 180 bottom
CB447  1uF/16V  [CC0402]  83.61 102.99 0 bottom
CB448  0.1uF/16V  [CC0402_22X22_8OCT]  28.7 124.18 90 bottom
CB449  22nF/16V  [CC0402_22X22_8OCT]  34.69 124.15 270 bottom
CB450  0.1uF/16V  [CC0402_22X22_8OCT]  42.7 124.15 90 bottom
CB451  0.1uF/16V  [CC0402_22X22_8OCT]  44.7 124.15 270 bottom
CB452  0.1uF/16V  [CC0402_22X22_8OCT]  46.7 124.15 270 bottom
CB453  0.1uF/16V  [CC0402_22X22_8OCT]  48.7 124.15 270 bottom
CB454  0.1uF/16V  [CC0402_22X22_8OCT]  23.62 124.13 270 bottom
CB455  0.1uF/16V  [CC0402]  60.8 123.8 90 bottom
CB456  @470pF  [CC0603]  122.04 172.63 270 bottom
CB457  0.1uF/16V  [CC0402_22X22_8OCT]  40.2 123.65 180 bottom
CB458  0.1uF/50V  [CC0402_22X22_8OCT]  41.2 123.65 0 bottom
CB459  22nF/16V  [CC0402_22X22_8OCT]  30.19 123.65 0 bottom
CB460  22nF/16V  [CC0402_22X22_8OCT]  31.19 123.65 180 bottom
CB461  22nF/16V  [CC0402_22X22_8OCT]  32.19 123.65 180 bottom
CB462  22nF/16V  [CC0402_22X22_8OCT]  33.19 123.65 180 bottom
CB463  0.1uF/16V  [CC0402_22X22_8OCT]  36.2 123.65 0 bottom
CB464  0.1uF/50V  [CC0402_22X22_8OCT]  37.2 123.65 0 bottom
CB465  22nF/16V  [CC0402_22X22_8OCT]  38.2 123.65 180 bottom
CB466  0.1uF/16V  [CC0402_22X22_8OCT]  28.7 123.17 90 bottom
CB467  0.1uF/16V  [CC0402_22X22_8OCT]  34.69 123.15 90 bottom
CB468  10nF/25V  [CC0402_22X22_8OCT]  44.7 123.15 90 bottom
CB469  0.1uF/50V  [CC0402_22X22_8OCT]  46.7 123.15 270 bottom
CB470  22nF/16V  [CC0402_22X22_8OCT]  52.71 123.15 270 bottom
CB471  0.1uF/16V  [CC0402_22X22_8OCT]  39.2 122.65 180 bottom
CB472  0.1uF/16V  [CC0402_22X22_8OCT]  26.19 122.65 180 bottom
CB473  4.7uF/6.3V  [CC0402_22X22_8OCT]  42.2 122.65 0 bottom
CB474  10nF/25V  [CC0402_22X22_8OCT]  43.2 122.65 180 bottom
CB475  22uF/10V  [CC1206]  76.29 122.27 0 bottom
CB476  22uF/25V  [CC1206]  78.45 122.27 180 bottom
CB477  22uF/10V  [CC1206]  80.61 122.27 0 bottom
CB478  0.1uF/16V  [CC0402_22X22_8OCT]  21.67 122.15 270 bottom
CB479  0.1uF/16V  [CC0402_22X22_8OCT]  48.72 122.15 270 bottom
CB480  0.1uF/50V  [CC0402_22X22_8OCT]  27.69 122.15 90 bottom
CB481  0.1uF/16V  [CC0402_22X22_8OCT]  33.69 122.15 270 bottom
CB482  0.1uF/16V  [CC0402_22X22_8OCT]  35.69 122.15 90 bottom
CB483  0.1uF/16V  [CC0402_22X22_8OCT]  37.7 122.15 90 bottom
CB484  10nF/25V  [CC0402_22X22_8OCT]  44.7 122.15 270 bottom
CB485  0.1uF/16V  [CC0402_22X22_8OCT]  46.7 122.15 270 bottom
CB486  1uF/16V  [CC0402_22X22_8OCT]  56.71 122.15 90 bottom
CB487  0.1uF/16V  [CC0402]  122.29 174.28 0 bottom
CB488  0.1uF/16V  [CC0402_22X22_8OCT]  32.22 121.72 180 bottom
CB489  0.1uF/16V  [CC0402_22X22_8OCT]  30.19 121.65 180 bottom
CB490  0.1uF/16V  [CC0402_22X22_8OCT]  31.19 121.65 180 bottom
CB491  1uF/16V  [CC0402_22X22_8OCT]  40.2 121.65 0 bottom
CB492  10nF/25V  [CC0402_22X22_8OCT]  41.2 121.65 0 bottom
CB493  22nF/16V  [CC0402_22X22_8OCT]  54.21 121.65 0 bottom
CB494  0.1uF/16V  [CC0402]  254.82 221.1 90 top
CB495  4.7uF/6.3V  [CC0402_22X22_8OCT]  33.69 121.15 270 bottom
CB496  0.1uF/16V  [CC0402_22X22_8OCT]  35.69 121.15 270 bottom
CB497  0.1uF/16V  [CC0402_22X22_8OCT]  37.7 121.15 270 bottom
CB498  0.1uF/16V  [CC0402_22X22_8OCT]  45.7 121.15 90 bottom
CB499  22nF/16V  [CC0402_22X22_8OCT]  51.71 121.15 270 bottom
CB500  1nF  [CC0402]  125.6 175.17 270 bottom
CB501  0.1uF/16V  [CC0402_22X22_8OCT]  50.24 120.66 180 bottom
CB502  22nF/16V  [CC0402_22X22_8OCT]  39.2 120.65 180 bottom
CB503  10nF/25V  [CC0402_22X22_8OCT]  42.2 120.65 0 bottom
CB504  10nF/25V  [CC0402_22X22_8OCT]  43.2 120.65 180 bottom
CB505  10nF/25V  [CC0402_22X22_8OCT]  44.2 120.65 0 bottom
CB506  22nF/16V  [CC0402_22X22_8OCT]  47.2 120.65 180 bottom
CB507  0.1uF/16V  [CC0402_22X22_8OCT]  48.2 120.65 180 bottom
CB508  0.1uF/16V  [CC0402_22X22_8OCT]  49.2 120.65 180 bottom
CB509  0.047uF  [CC0402]  41.54 195.76 270 bottom
CB510  0.1uF/16V  [CC0402_22X22_8OCT]  45.7 120.15 90 bottom
CB511  0.1uF/16V  [CC0402]  65.31 121.32 0 top
CB512  22nF/16V  [CC0402_22X22_8OCT]  29.19 119.69 180 bottom
CB513  22nF/16V  [CC0402_22X22_8OCT]  30.19 119.65 180 bottom
CB514  22nF/16V  [CC0402_22X22_8OCT]  31.19 119.65 0 bottom
CB515  22nF/16V  [CC0402_22X22_8OCT]  32.19 119.65 180 bottom
CB516  22nF/16V  [CC0402_22X22_8OCT]  33.19 119.65 0 bottom
CB517  22nF/16V  [CC0402_22X22_8OCT]  34.19 119.65 180 bottom
CB518  22nF/16V  [CC0402_22X22_8OCT]  35.19 119.65 0 bottom
CB519  1uF/16V  [CC0402_22X22_8OCT]  36.2 119.65 0 bottom
CB520  10nF/25V  [CC0402_22X22_8OCT]  37.2 119.65 0 bottom
CB521  1uF/16V  [CC0402_22X22_8OCT]  38.2 119.65 0 bottom
CB522  0.1uF/16V  [CC0402]  162.46 133.59 0 bottom
CB523  0.1uF/16V  [CC0402_22X22_8OCT]  26.75 119.15 270 bottom
CB524  0.1uF/16V  [CC0402_22X22_8OCT]  46.7 119.15 90 bottom
CB525  0.1uF/16V  [CC0402_22X22_8OCT]  48.7 119.15 270 bottom
CB526  22nF/16V  [CC0402_22X22_8OCT]  56.64 119.1 270 bottom
CB527  0.1uF/16V  [CC0402]  95.6 119.1 0 bottom
CB528  0.1uF/16V  [CC0402]  64.29 121.32 0 top
CB529  0.1uF/16V  [CC0402_22X22_8OCT]  28.19 118.65 180 bottom
CB530  1uF/16V  [CC0402_22X22_8OCT]  39.2 118.65 0 bottom
CB531  4.7uF/6.3V  [CC0402_22X22_8OCT]  41.2 118.65 0 bottom
CB532  10nF/25V  [CC0402_22X22_8OCT]  42.2 118.65 0 bottom
CB533  4.7uF/6.3V  [CC0402_22X22_8OCT]  43.2 118.65 180 bottom
CB534  10nF/25V  [CC0402_22X22_8OCT]  44.2 118.65 0 bottom
CB535  10nF/25V  [CC0402_22X22_8OCT]  45.2 118.65 180 bottom
CB536  22nF/16V  [CC0402_22X22_8OCT]  50.21 118.65 180 bottom
CB537  22nF/16V  [CC0402_22X22_8OCT]  53.21 118.65 180 bottom
CB538  4.7uF/6.3V  [CC0402_22X22_8OCT]  40.24 118.61 0 bottom
CB539  0.1uF/16V  [CC0402_22X22_8OCT]  47.65 118.16 90 bottom
CB540  22nF/16V  [CC0402_22X22_8OCT]  31.69 118.15 90 bottom
CB541  22nF/16V  [CC0402_22X22_8OCT]  33.69 118.15 90 bottom
CB542  22nF/16V  [CC0402_22X22_8OCT]  35.69 118.15 90 bottom
CB543  10nF/25V  [CC0402_22X22_8OCT]  37.7 118.15 90 bottom
CB544  0.1uF/16V  [CC0402_22X22_8OCT]  21.64 118.14 270 bottom
CB545  0.1uF/25V  [CC0402]  118.48 178.48 90 top
CB546  0.1uF/16V  [CC0402_22X22_8OCT]  24.18 117.71 0 bottom
CB547  4.7uF/6.3V  [CC0402_22X22_8OCT]  25.2 117.71 0 bottom
CB548  0.1uF/50V  [CC0402_22X22_8OCT]  26.22 117.71 180 bottom
CB549  4.7uF/6.3V  [CC0402_22X22_8OCT]  46.2 117.65 180 bottom
CB550  22uF /25V  [CC1206]  99.63 110.72 270 bottom
CB551  1uF/16V  [CC0402_22X22_8OCT]  52.71 117.2 270 bottom
CB552  1uF/16V  [CC0402_22X22_8OCT]  30.7 117.15 90 bottom
CB553  10nF/25V  [CC0402_22X22_8OCT]  35.69 117.15 270 bottom
CB554  22nF/16V  [CC0402_22X22_8OCT]  37.7 117.15 270 bottom
CB555  47nF/16V  [CC0402_22X22_8OCT]  43.7 117.15 270 bottom
CB556  4.7uF/6.3V  [CC0402_22X22_8OCT]  47.7 117.15 270 bottom
CB557  1uF/16V  [CC0402_22X22_8OCT]  21.21 116.69 0 bottom
CB558  0.22uF/6.3V  [CC0402_22X22_8OCT]  45.2 116.65 180 bottom
CB559  0.1uF/50V  [CC0402_22X22_8OCT]  41.25 116.64 0 bottom
CB560  0.1uF/16V  [CC0402_22X22_8OCT]  42.27 116.64 180 bottom
CB561  22uF /25V  [CC1206]  170.75 116.62 0 bottom
CB562  22uF /25V  [CC1206]  172.78 116.62 0 bottom
CB563  22uF /25V  [CC1206]  175.07 116.62 0 bottom
CB564  0.1uF/16V  [CC0402]  59.25 116.3 90 bottom
CB565  22nF/16V  [CC0402_22X22_8OCT]  31.69 116.15 90 bottom
CB566  10nF/25V  [CC0402_22X22_8OCT]  33.69 116.15 90 bottom
CB567  10nF/25V  [CC0402_22X22_8OCT]  35.69 116.15 90 bottom
CB568  1uF/16V  [CC0402_22X22_8OCT]  37.7 116.15 270 bottom
CB569  47nF/16V  [CC0402_22X22_8OCT]  43.7 116.15 90 bottom
CB570  22uF/25V  [CC1206]  118.86 182.46 270 top
CB571  10nF/25V  [CC0402_22X22_8OCT]  30.23 115.67 0 bottom
CB572  2.2uF/16V  [CC0603]  96.87 115.67 0 bottom
CB573  47nF/16V  [CC0402_22X22_8OCT]  47.2 115.65 0 bottom
CB574  1uF/16V  [CC0402_22X22_8OCT]  24.22 115.29 270 bottom
CB575  0.1uF/16V  [CC0402]  59.25 115.29 90 bottom
CB576  1uF/16V  [CC0402_22X22_8OCT]  50.68 115.17 270 bottom
CB577  1uF/16V  [CC0402_22X22_8OCT]  54.61 115.17 270 bottom
CB578  1nF/50V  [CC0402]  95.6 115.16 180 bottom
CB579  0.1uF/25V  [CC0402]  169.04 115.09 180 bottom
CB580  10nF/25V  [CC0402_22X22_8OCT]  34.69 115.15 90 bottom
CB581  10nF/25V  [CC0402_22X22_8OCT]  36.7 115.15 90 bottom
CB582  47nF/16V  [CC0402_22X22_8OCT]  41.7 115.15 270 bottom
CB583  47nF/16V  [CC0402_22X22_8OCT]  43.7 115.15 270 bottom
CB584  1000pF  [CC0603]  161.89 118.34 270 bottom
CB585  0.1uF/50V  [CC0402_22X22_8OCT]  33.19 114.64 180 bottom
CB586  0.1uF/16V  [CC0402]  59.33 111.87 180 bottom
CB587  470uF/2V  [CAP_6D4_2SP_4D3W7D3L2D1H]  77.44 114.15 90 bottom
CB588  470uF/2V  [CAP_6D4_2SP_4D3W7D3L2D1H]  82.39 114.15 90 bottom
CB589  10nF/25V  [CC0402_22X22_8OCT]  36.7 114.14 270 bottom
CB590  47nF/16V  [CC0402_22X22_8OCT]  38.67 114.17 270 bottom
CB591  0.47uF/16V  [CC0402_22X22_8OCT]  40.7 114.14 270 bottom
CB592  0.47uF/16V  [CC0402_22X22_8OCT]  42.7 114.14 270 bottom
CB593  1uF/16V  [CC0402_22X22_8OCT]  52.76 114.1 90 bottom
CB594  22uF/25V  [CC1206]  118.87 182.49 90 bottom
CB595  0.1uF/16V  [CC0402_22X22_8OCT]  25.28 113.67 180 bottom
CB596  0.1uF/16V  [CC0402_22X22_8OCT]  26.27 113.67 180 bottom
CB597  4.7uF/6.3V  [CC0402_22X22_8OCT]  27.28 113.67 180 bottom
CB598  1uF/16V  [CC0402_22X22_8OCT]  23.24 113.66 180 bottom
CB599  10nF/25V  [CC0402_22X22_8OCT]  30.19 113.64 0 bottom
CB600  10nF/25V  [CC0402_22X22_8OCT]  31.19 113.64 0 bottom
CB601  4.7uF/6.3V  [CC0402_22X22_8OCT]  32.19 113.64 180 bottom
CB602  1uF/16V  [CC0402_22X22_8OCT]  54.21 113.64 0 bottom
CB603  1uF/16V  [CC0402_22X22_8OCT]  21.21 113.64 180 bottom
CB604  1uF/16V  [CC0402_22X22_8OCT]  22.25 113.64 180 bottom
CB605  0.1uF/50V  [CC0402_22X22_8OCT]  45.21 113.64 180 bottom
CB606  1uF/16V  [CC0402_22X22_8OCT]  49.15 113.64 0 bottom
CB607  0.1uF/16V  [CC0402]  60.34 111.87 180 bottom
CB608  1uF/16V  [CC0402_22X22_8OCT]  57.2 112.65 0 bottom
CB609  10nF/25V  [CC0402_22X22_8OCT]  35.69 113.14 270 bottom
CB610  0.22uF/6.3V  [CC0402_22X22_8OCT]  37.7 113.14 270 bottom
CB611  0.47uF/16V  [CC0402_22X22_8OCT]  39.7 113.14 270 bottom
CB612  0.22uF/6.3V  [CC0402_22X22_8OCT]  41.7 113.14 270 bottom
CB613  0.47uF/16V  [CC0402_22X22_8OCT]  43.7 113.14 270 bottom
CB614  1uF/16V  [CC0402_22X22_8OCT]  50.68 113.13 270 bottom
CB615  47nF/16V  [CC0402_22X22_8OCT]  46.2 112.64 0 bottom
CB616  47nF/16V  [CC0402_22X22_8OCT]  47.2 112.64 180 bottom
CB617  1uF/16V  [CC0402_22X22_8OCT]  56.21 112.64 0 bottom
CB618  22uF /25V  [CC1206]  99.64 113.04 270 bottom
CB619  10nF/25V  [CC0402_22X22_8OCT]  31.69 112.14 90 bottom
CB620  10nF/25V  [CC0402_22X22_8OCT]  33.69 112.14 90 bottom
CB621  10nF/25V  [CC0402_22X22_8OCT]  35.69 112.14 90 bottom
CB622  0.22uF/6.3V  [CC0402_22X22_8OCT]  37.7 112.14 90 bottom
CB623  0.22uF/6.3V  [CC0402_22X22_8OCT]  39.7 112.14 90 bottom
CB624  0.22uF/6.3V  [CC0402_22X22_8OCT]  41.7 112.14 90 bottom
CB625  0.22uF/6.3V  [CC0402_22X22_8OCT]  43.7 112.14 90 bottom
CB626  10nF/25V  [CC0402_22X22_8OCT]  31.69 111.14 270 bottom
CB627  10nF/25V  [CC0402_22X22_8OCT]  37.7 111.14 270 bottom
CB628  0.22uF/6.3V  [CC0402_22X22_8OCT]  40.7 111.14 90 bottom
CB629  0.22uF/6.3V  [CC0402_22X22_8OCT]  42.7 111.14 90 bottom
CB630  47nF/16V  [CC0402_22X22_8OCT]  44.7 111.14 90 bottom
CB631  47nF/16V  [CC0402_22X22_8OCT]  46.7 111.14 90 bottom
CB632  1uF/16V  [CC0402_22X22_8OCT]  51.71 111.14 90 bottom
CB633  1uF/16V  [CC0402_22X22_8OCT]  56.71 111.14 90 bottom
CB634  1uF/16V  [CC0402_22X22_8OCT]  49.71 111.12 270 bottom
CB635  1uF/16V  [CC0402_22X22_8OCT]  54.71 111.12 270 bottom
CB636  1uF/16V  [CC0402_22X22_8OCT]  22.68 111.1 270 bottom
CB637  1uF/16V  [CC0402_22X22_8OCT]  24.69 111.1 90 bottom
CB638  1uF/16V  [CC0402_22X22_8OCT]  27.69 111.1 270 bottom
CB639  1uF/16V  [CC0402_22X22_8OCT]  29.72 111.1 90 bottom
CB640  0.47uF/16V  [CC0402_22X22_8OCT]  39.2 110.64 180 bottom
CB641  0.1uF/50V  [CC0402_22X22_8OCT]  34.19 110.64 180 bottom
CB642  0.1uF/16V  [CC0402_22X22_8OCT]  35.19 110.64 0 bottom
CB643  10nF/25V  [CC0402_22X22_8OCT]  31.69 110.14 270 bottom
CB644  0.22uF/6.3V  [CC0402_22X22_8OCT]  44.7 110.14 270 bottom
CB645  47nF/16V  [CC0402_22X22_8OCT]  46.7 110.14 270 bottom
CB646  1uF  [CC0402_22X22_8OCT]  41.2 109.64 180 bottom
CB647  1uF/16V  [CC0402_22X22_8OCT]  57.74 109.17 90 bottom
CB648  1uF/16V  [CC0402_22X22_8OCT]  51.71 109.17 270 bottom
CB649  1uF/16V  [CC0402_22X22_8OCT]  53.71 109.17 90 bottom
CB650  1uF/16V  [CC0402_22X22_8OCT]  24.77 109.15 270 bottom
CB651  1uF/16V  [CC0402_22X22_8OCT]  26.75 109.15 90 bottom
CB652  1uF/16V  [CC0402_22X22_8OCT]  55.76 109.12 270 bottom
CB653  1uF/16V  [CC0402_22X22_8OCT]  22.74 109.1 90 bottom
CB654  0.1uF/25V  [CC0402]  113.38 108.81 90 bottom
CB655  1uF  [CC0402_22X22_8OCT]  42.17 108.69 0 bottom
CB656  1uF  [CC0402_22X22_8OCT]  37.2 108.64 180 bottom
CB657  1uF  [CC0402_22X22_8OCT]  39.2 108.64 0 bottom
CB658  1uF  [CC0402_22X22_8OCT]  40.2 108.64 0 bottom
CB659  1uF/16V  [CC0402_22X22_8OCT]  45.2 108.64 0 bottom
CB660  1uF/16V  [CC0402_22X22_8OCT]  46.2 108.64 0 bottom
CB661  0.1uF/16V  [CC0402_22X22_8OCT]  34.22 108.6 180 bottom
CB662  0.1uF/16V  [CC0402_22X22_8OCT]  35.19 108.6 180 bottom
CB663  1uF/16V  [CC0402_22X22_8OCT]  20.03 108.56 0 bottom
CB664  1uF/16V  [CC0402_22X22_8OCT]  47.7 108.14 270 bottom
CB665  1uF/16V  [CC0402_22X22_8OCT]  30.71 108.08 270 bottom
CB666  1uF/16V  [CC0402_22X22_8OCT]  32.18 107.6 0 bottom
CB667  1uF/16V  [CC0402_22X22_8OCT]  33.2 107.6 0 bottom
CB673  1uF/16V  [CC0402_22X22_8OCT]  21.21 106.66 180 bottom
CB674  1uF/16V  [CC0402_22X22_8OCT]  22.23 106.66 180 bottom
CB675  1uF/16V  [CC0402_22X22_8OCT]  35.21 106.66 180 bottom
CB676  1uF/16V  [CC0402_22X22_8OCT]  36.17 106.64 180 bottom
CB677  1uF/16V  [CC0402_22X22_8OCT]  41.17 106.64 180 bottom
CB678  1uF/16V  [CC0402_22X22_8OCT]  45.18 106.64 180 bottom
CB679  1uF/16V  [CC0402_22X22_8OCT]  49.18 106.64 180 bottom
CB680  1uF/16V  [CC0402_22X22_8OCT]  31.17 106.61 0 bottom
CB682  1uF/16V  [CC0402_22X22_8OCT]  25.22 105.69 180 bottom
CB683  1uF/16V  [CC0402_22X22_8OCT]  29.21 105.69 180 bottom
CB684  1uF/16V  [CC0402_22X22_8OCT]  53.16 105.64 180 bottom
CB685  1uF/16V  [CC0402_22X22_8OCT]  57.19 105.64 180 bottom
CB686  0.1uF  [CC0402]  112.81 94.84 0 bottom
CB688  1uF/16V  [CC0402_22X22_8OCT]  36.2 104.64 0 bottom
CB689  1uF/16V  [CC0402_22X22_8OCT]  41.17 104.64 0 bottom
CB690  1uF/16V  [CC0402_22X22_8OCT]  45.2 104.64 0 bottom
CB691  1uF/16V  [CC0402_22X22_8OCT]  47.2 104.64 180 bottom
CB692  1uF/16V  [CC0402_22X22_8OCT]  49.2 104.64 0 bottom
CB693  1uF/16V  [CC0402_22X22_8OCT]  21.21 104.63 0 bottom
CB694  1uF/16V  [CC0402_22X22_8OCT]  31.24 104.63 180 bottom
CB695  1uF/16V  [CC0402_22X22_8OCT]  48.19 104.63 180 bottom
CB696  1uF/16V  [CC0402_22X22_8OCT]  55.71 104.14 270 bottom
CB697  1uF/16V  [CC0402_22X22_8OCT]  23.19 103.71 180 bottom
CB698  1uF/16V  [CC0402_22X22_8OCT]  25.15 103.69 0 bottom
CB699  1uF/16V  [CC0402_22X22_8OCT]  27.18 103.69 180 bottom
CB700  1uF/16V  [CC0402_22X22_8OCT]  29.19 103.69 0 bottom
CB701  1uF/16V  [CC0402_22X22_8OCT]  35.17 103.64 180 bottom
CB702  1uF/16V  [CC0402_22X22_8OCT]  40.17 103.64 180 bottom
CB703  1uF/16V  [CC0402_22X22_8OCT]  44.18 103.64 180 bottom
CB704  1uF/16V  [CC0402_22X22_8OCT]  51.21 103.64 180 bottom
CB705  1uF/16V  [CC0402_22X22_8OCT]  53.21 103.64 0 bottom
CB706  1uF/16V  [CC0402_22X22_8OCT]  57.21 103.64 0 bottom
CB707  1uF  [CC0402]  196 98.96 270 top
CB708  0.01uF/25V  [CC0402]  196 97.94 270 top
CB712  1000pF/100V  [CC0603]  172.74 102.38 180 bottom
CB713  1uF/16V  [CC0402_22X22_8OCT]  52.17 102.64 0 bottom
CB714  1uF/16V  [CC0402_22X22_8OCT]  47.23 102.64 0 bottom
CB715  1uF/16V  [CC0402_22X22_8OCT]  31.14 102.62 0 bottom
CB716  1uF/16V  [CC0402_22X22_8OCT]  55.71 102.14 90 bottom
CB717  1uF/16V  [CC0402_22X22_8OCT]  25.22 101.7 180 bottom
CB718  1uF/16V  [CC0402_22X22_8OCT]  27.18 101.7 0 bottom
CB719  1uF/16V  [CC0402_22X22_8OCT]  29.21 101.7 180 bottom
CB720  1uF/16V  [CC0402_22X22_8OCT]  51.18 101.7 0 bottom
CB721  1uF/16V  [CC0402_22X22_8OCT]  23.19 101.68 0 bottom
CB722  1uF/16V  [CC0402_22X22_8OCT]  41.23 101.68 180 bottom
CB723  1uF/16V  [CC0402_22X22_8OCT]  48.16 101.68 180 bottom
CB724  1uF/16V  [CC0402_22X22_8OCT]  35.19 101.64 0 bottom
CB725  1uF/16V  [CC0402_22X22_8OCT]  40.17 101.64 0 bottom
CB726  1uF/16V  [CC0402_22X22_8OCT]  44.2 101.64 0 bottom
CB727  1uF/16V  [CC0402_22X22_8OCT]  49.2 101.64 180 bottom
CB728  1uF/16V  [CC0402_22X22_8OCT]  36.2 101.63 180 bottom
CB729  1uF/16V  [CC0402_22X22_8OCT]  45.21 101.63 180 bottom
CB731  @1000pF  [CC0603]  112.11 101.19 180 bottom
CB732  1uF/16V  [CC0402_22X22_8OCT]  56.71 101.13 90 bottom
CB733  10uF/16V  [CC0805]  196.39 100.53 90 top
CB734  1uF/16V  [CC0402_22X22_8OCT]  21.21 100.69 180 bottom
CB735  1uF/16V  [CC0402_22X22_8OCT]  53.18 100.63 180 bottom
CB738  10uF/6.3V  [CC0805]  83.53 100.05 0 bottom
